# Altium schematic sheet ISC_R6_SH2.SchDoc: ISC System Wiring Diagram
size B; DrawnBy: Filiberto Clara; Engineer: Filiberto Clara; Organization: LIGO Laboratory; Address1: California Institute of Technology; Address2: Massachusetts Institute of Technology; SheetNumber: 23; SheetTotal: 39
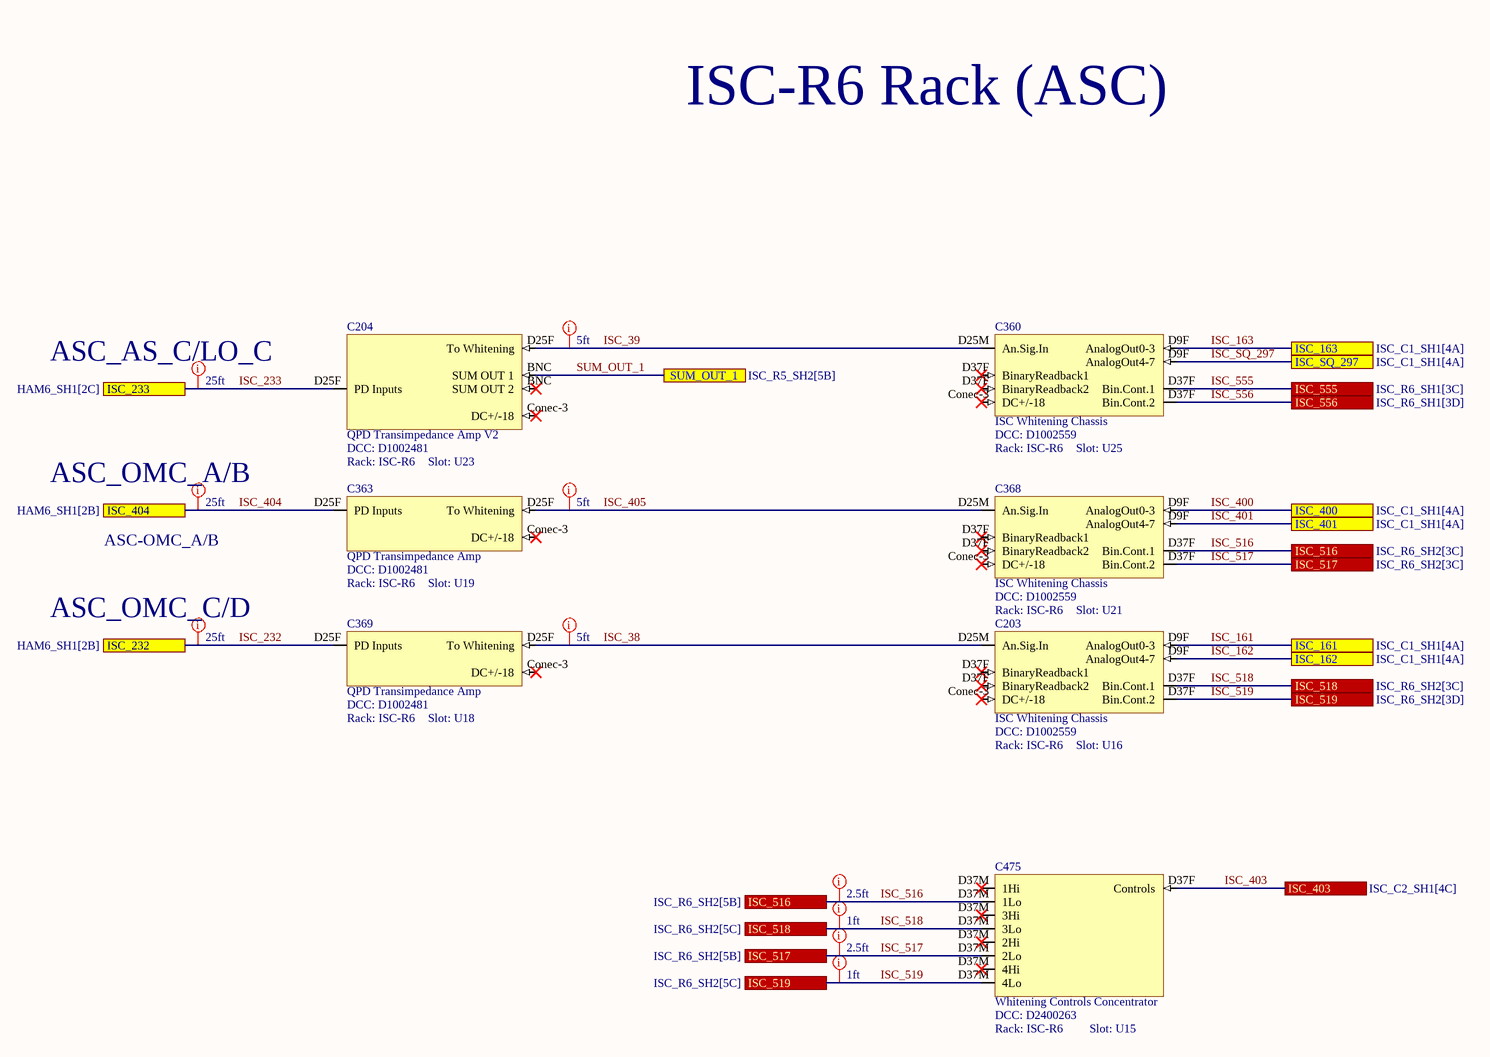
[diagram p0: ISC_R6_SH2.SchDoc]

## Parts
C203  ISC Whitening Chassis  DCC: D1002559  Rack: ISC-R6  Slot: U16
C204  QPD Transimpedance Amp V2  DCC: D1002481  Rack: ISC-R6  Slot: U23
C360  ISC Whitening Chassis  DCC: D1002559  Rack: ISC-R6  Slot: U25
C363  QPD Transimpedance Amp  DCC: D1002481  Rack: ISC-R6  Slot: U19
C368  ISC Whitening Chassis  DCC: D1002559  Rack: ISC-R6  Slot: U21
C369  QPD Transimpedance Amp  DCC: D1002481  Rack: ISC-R6  Slot: U18
C475  Whitening Controls Concentrator  DCC: D2400263  Rack: ISC-R6  Slot: U15

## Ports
ISC_161 (see ISC_C1_SH1[4A]), ISC_162 (see ISC_C1_SH1[4A]), ISC_163 (see ISC_C1_SH1[4A]), ISC_232 (see HAM6_SH1[2B]), ISC_233 (see HAM6_SH1[2C]), ISC_400 (see ISC_C1_SH1[4A]), ISC_401 (see ISC_C1_SH1[4A]), ISC_403 (see ISC_C2_SH1[4C]), ISC_404 (see HAM6_SH1[2B]), ISC_516 (see ISC_R6_SH2[3C]), ISC_516 (see ISC_R6_SH2[5B]), ISC_517 (see ISC_R6_SH2[3C]), ISC_517 (see ISC_R6_SH2[5B]), ISC_518 (see ISC_R6_SH2[3C]), ISC_518 (see ISC_R6_SH2[5C]), ISC_519 (see ISC_R6_SH2[3D]), ISC_519 (see ISC_R6_SH2[5C]), ISC_555 (see ISC_R6_SH1[3C]), ISC_556 (see ISC_R6_SH1[3D]), ISC_SQ_297 (see ISC_C1_SH1[4A]), SUM_OUT_1 (see ISC_R5_SH2[5B])

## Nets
ISC_38: C203.D25M(An.Sig.In) C369.D25F(To_Whitening)
ISC_39: C204.D25F(To_Whitening) C360.D25M(An.Sig.In)
ISC_161: C203.D9F(AnalogOut0-3) ; port ISC_161
ISC_162: C203.D9F(AnalogOut4-7) ; port ISC_162
ISC_163: C360.D9F(AnalogOut0-3) ; port ISC_163
ISC_232: C369.D25F(PD_Inputs) ; port ISC_232
ISC_233: C204.D25F(PD_Inputs) ; port ISC_233
ISC_400: C368.D9F(AnalogOut0-3) ; port ISC_400
ISC_401: C368.D9F(AnalogOut4-7) ; port ISC_401
ISC_403: C475.D37F(Controls) ; port ISC_403
ISC_404: C363.D25F(PD_Inputs) ; port ISC_404
ISC_405: C363.D25F(To_Whitening) C368.D25M(An.Sig.In)
ISC_516: C368.D37F(BinaryReadback1) C475.D37M(1Hi) ; port ISC_516
ISC_517: C368.D37F(Bin.Cont.2) C475.D37M(2Lo) ; port ISC_517
ISC_518: C203.D37F(BinaryReadback1) C475.D37M(3Lo) ; port ISC_518
ISC_519: C203.D37F(Bin.Cont.2) C475.D37M(4Lo) ; port ISC_519
ISC_555: C360.D37F(BinaryReadback1) ; port ISC_555
ISC_556: C360.D37F(Bin.Cont.2) ; port ISC_556
ISC_SQ_297: C360.D9F(AnalogOut4-7) ; port ISC_SQ_297
SUM_OUT_1: C204.BNC(SUM_OUT_1) ; port SUM_OUT_1

Not connected (* = marked no-connect by the designer): C203 Conec-3(DC+/-18)*; C204 Conec-3(DC+/-18)*; C360 Conec-3(DC+/-18)*; C363 Conec-3(DC+/-18)*; C368 Conec-3(DC+/-18)*; C369 Conec-3(DC+/-18)*

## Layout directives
Length: 5ft: ISC_38, ISC_39, ISC_405
Length: 25ft: ISC_232, ISC_233, ISC_404
Length: 2.5ft: ISC_516, ISC_517
Length: 1ft: ISC_518, ISC_519

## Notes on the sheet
- ISC-R6 Rack (ASC)
- ASC_AS_C/LO_C
- ASC_OMC_A/B
- ASC-OMC_A/B
- ASC_OMC_C/D

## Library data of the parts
C203 C360 C368 = ISC Whitening: Serial: Sxxxxxxx
C204 = QPD Transimpedance Amp V2: Serial: Sxxxxxxx; System: ISC
C363 C369 = QPD Transimpedance Amp: Serial: Sxxxxxxx; System: ISC
C475 = Whitening Controls Concentrator: Serial: Sxxxxxxx; System: ISC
